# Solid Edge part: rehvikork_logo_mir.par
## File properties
Author: KULL
Template: Iso Metric Part.par
Last saved by: KULL
Revision: 2
Application: Solid Edge
Accuracy: 0,990
Username: KULL
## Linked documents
rehvikork_logo.par
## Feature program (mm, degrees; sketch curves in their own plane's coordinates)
part copy "CopiedPart_1"
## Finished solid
Body 1: solid body, 86 faces, 199 edges, 116 vertices, 2 separate solids.
  Faces by surface: spline 40, blend 36, sphere 8, cone 1, torus 1
  Edges by curve: intersection 112, line 32, circle 29, curve on surface 26
Bounding box of the edges (mm; curved faces can reach further): 1.405 x 13.917 x 13.917, from (-0.4589, -6.9587, -6.9587) to (0.946, 6.9587, 6.9587).
Conical faces (half-angle, radius in mm at the cone's reference point): 11.8765 deg R7 x1
Toroidal faces (ring radius, tube radius in mm): R6.763 r0.2 x1
Spherical faces by radius (mm): R0.2 x4, R33.3132 x2, R34.0132 x2
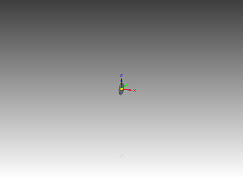
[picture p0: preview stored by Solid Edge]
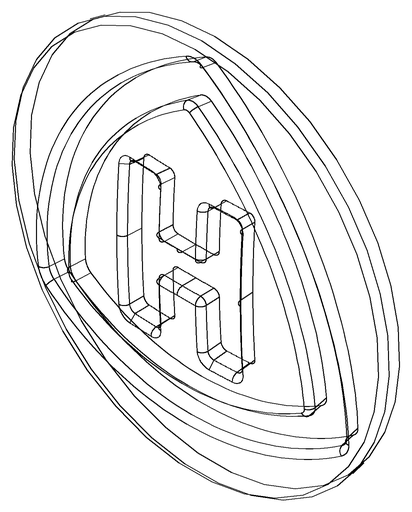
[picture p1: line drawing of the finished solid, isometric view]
